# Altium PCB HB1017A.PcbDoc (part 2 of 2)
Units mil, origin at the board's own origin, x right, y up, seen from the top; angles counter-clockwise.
Board outline 2906.96 x 3469.35 mil, 2 copper layers (Top Layer, Bottom Layer); 52 components, 64 nets, 277 pads, 519 vias.
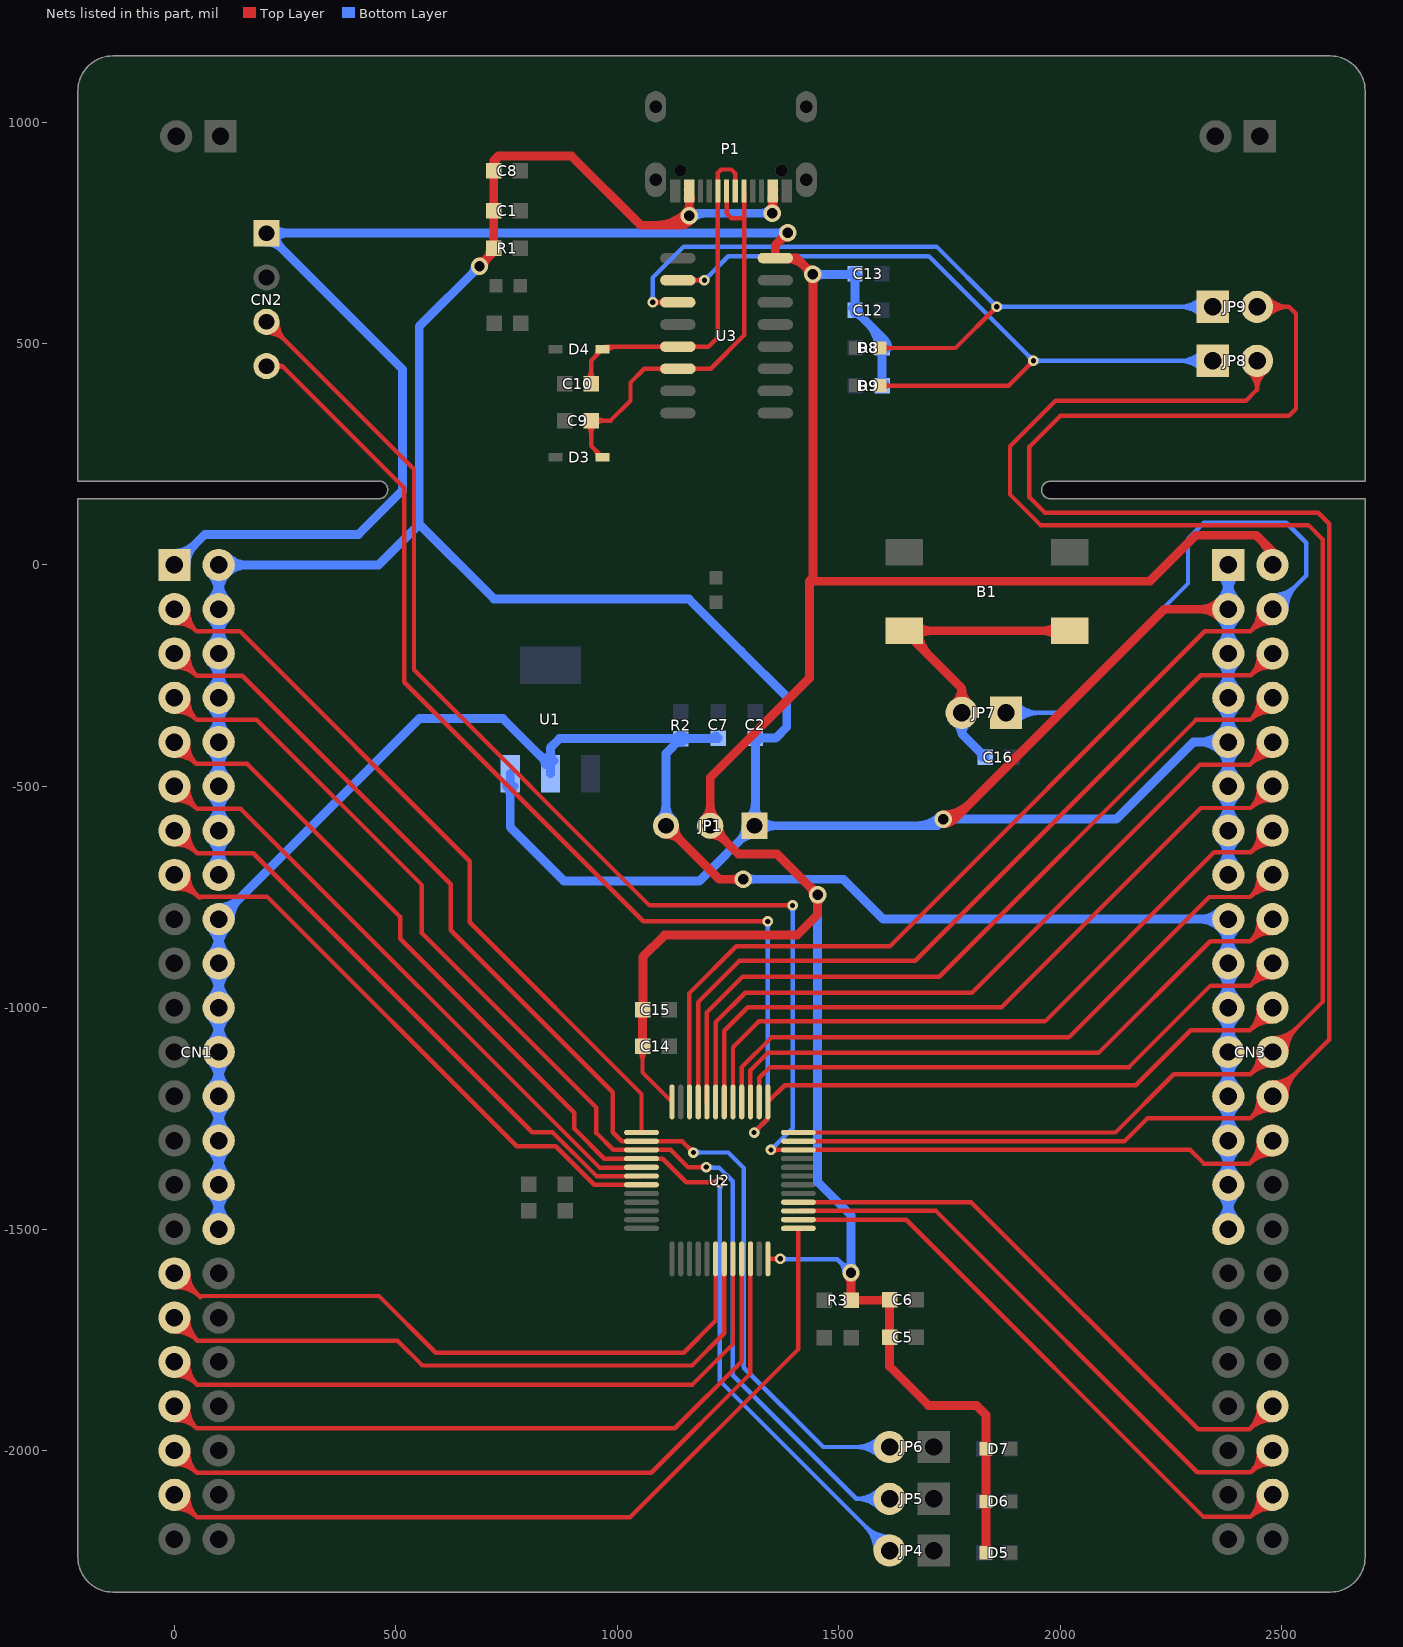
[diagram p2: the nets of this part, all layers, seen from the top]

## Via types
v1: diameter 23.62, hole 11.81, Top Layer to Bottom Layer, tented both sides, 489 vias
v2: diameter 39.37, hole 23.62, Top Layer to Bottom Layer, tented both sides, 30 vias

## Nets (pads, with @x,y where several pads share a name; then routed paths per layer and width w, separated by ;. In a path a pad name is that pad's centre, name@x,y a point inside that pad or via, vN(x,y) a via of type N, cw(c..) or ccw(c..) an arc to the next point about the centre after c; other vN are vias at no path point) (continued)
PA13: CN2.3 CN3.28 U2.34 | length 4181.5
  Top Layer w10: CN2.3@208,524.47 cw(c208,465.26) 249.87,507.13 cw(c291.74,549) CN2.3@232.53,549 ; CN2.3@208,534.47 cw(c208,499.4) 232.8,524.2 cw(c257.6,549) CN2.3@222.53,549 ; CN2.3@208,549 541,216 541,-237 1073,-769 v1(1396,-769) ; v1(1347,-1321.1) U2.34@1409.17,-1321.1 2294.14,-1321.1 2325.04,-1352 2428,-1352 ; v1@1351.82,-1325.92 cw(c1363.44,-1337.55) 1363.44,-1321.1 cw(c1363.44,-1304.66) v1@1351.82,-1316.29 ; v1@1391.18,-773.82 ccw(c1379.56,-785.44) 1379.56,-769 ccw(c1379.56,-752.56) v1@1391.18,-764.18 ; CN3.28@2448.59,-1300.7 cw(c2378.26,-1302.25) 2428,-1352 ; CN3.28@2458.59,-1300.47 cw(c2410.64,-1301.54) 2444.55,-1335.45 cw(c2478.46,-1369.36) CN3.28@2479.53,-1321.41 ; CN3.28@2479.3,-1331.41 ccw(c2477.75,-1401.74) 2428,-1352 ; CN3.28@2480,-1300 2428,-1352
  Bottom Layer w10: v1(1347,-1321.1) 1396,-1272.1 v1(1396,-769) ; v1@1347,-1314.29 ccw(c1347,-1297.85) 1358.63,-1309.47 ccw(c1370.25,-1321.1) v1@1353.81,-1321.1 ; v1@1391.18,-773.82 cw(c1379.56,-785.44) 1396,-785.44 cw(c1412.44,-785.44) v1@1400.82,-773.82
PA14: CN2.4 CN3.22 U2.37 | length 4041.1
  Top Layer w10: CN2.4@208,449 244,449 ; CN2.4@230.83,440.03 cw(c244,434.85) 244,449 ; CN2.4@230.83,457.97 ccw(c244,463.15) 244,449 ; v1(1309,-1282) 1340.27,-1250.73 U2.37@1340.27,-1212.83 1378.1,-1175 2171,-1175 2295,-1051 2429,-1051 ; v1@1309,-1275.19 ccw(c1309,-1258.75) 1320.63,-1270.37 ccw(c1332.25,-1282) v1@1315.81,-1282 ; v1@1335.18,-809.82 ccw(c1323.56,-821.44) 1323.56,-805 ccw(c1323.56,-788.56) v1@1335.18,-800.18 ; 1335.59,-1255.41 ccw(c1326.47,-1246.3) U2.37@1339.36,-1246.3 ; v1(1340,-805) 1059,-805 519,-265 519,174 244,449 ; CN3.22@2448.6,-1001.14 cw(c2381.58,-1003.57) 2429,-1051 ; CN3.22@2458.6,-1000.78 cw(c2412.9,-1002.43) 2445.24,-1034.76 cw(c2477.57,-1067.1) CN3.22@2479.22,-1021.4 ; CN3.22@2478.86,-1031.4 ccw(c2476.43,-1098.42) 2429,-1051 ; CN3.22@2480,-1000 2429,-1051
  Bottom Layer w10: v1(1309,-1282) 1340,-1251 v1(1340,-805) ; v1@1309,-1275.19 ccw(c1309,-1258.75) 1320.63,-1270.37 ccw(c1332.25,-1282) v1@1315.81,-1282 ; v1@1335.18,-809.82 cw(c1323.56,-821.44) 1340,-821.44 cw(c1356.44,-821.44) v1@1344.82,-809.82
PA15: CN3.20 U2.38 | length 1500.5
  Top Layer w10: U2.38@1320.58,-1212.83 1321,-1212.42 1321,-1158 1345,-1134 2156,-1134 2340,-950 2430,-950 ; CN3.20@2448.62,-901.6 cw(c2384.85,-904.84) 2430,-950 ; CN3.20@2458.61,-901.09 cw(c2415.13,-903.3) 2445.92,-934.08 cw(c2476.7,-964.87) CN3.20@2478.91,-921.39 ; CN3.20@2478.4,-931.38 ccw(c2475.16,-995.15) 2430,-950 ; CN3.20@2480,-900 2430,-950
PB0: CN1.33 U2.18 | length 1655.8
  Top Layer w10: CN1.33@0,-1600 5.17,-1600 56.17,-1651 462,-1651 590,-1779 1150,-1779 1222.16,-1706.84 U2.18@1222.16,-1567.17 ; CN1.33@0.99,-1621.39 cw(c3.55,-1676.75) 42.73,-1637.57 ; CN1.33@1.45,-1631.38 cw(c4.96,-1707.36) 58.75,-1653.58 ; CN1.33@21.42,-1600 ccw(c60.65,-1600) 32.91,-1627.74 ; CN1.33@31.42,-1600 ccw(c94.8,-1600) 49.98,-1644.81
PB1: CN1.35 U2.19 | length 1675.8
  Top Layer w10: CN1.35@0,-1700 52,-1752 ; CN1.35@0.47,-1721.41 cw(c1.54,-1769.36) 35.45,-1735.45 cw(c69.36,-1701.54) CN1.35@21.41,-1700.47 ; CN1.35@0.7,-1731.41 cw(c2.25,-1801.74) 52,-1752 ; CN1.35@31.41,-1700.7 ccw(c101.74,-1702.25) 52,-1752 ; U2.19@1241.84,-1567.17 1241.84,-1735.16 1169,-1808 560,-1808 504,-1752 52,-1752
PB2: CN1.37 U2.20 | length 1698.2
  Top Layer w10: CN1.37@0,-1800 51,-1851 ; CN1.37@0.78,-1821.4 cw(c2.43,-1867.1) 34.76,-1834.76 cw(c67.1,-1802.43) CN1.37@21.4,-1800.78 ; CN1.37@1.14,-1831.4 cw(c3.57,-1898.42) 51,-1851 ; CN1.37@31.4,-1801.14 ccw(c98.42,-1803.57) 51,-1851 ; U2.20@1261.53,-1567.17 1261.53,-1759.47 1170,-1851 51,-1851
PB3: CN3.18 U2.39 | length 1571.7
  Top Layer w10: U2.39@1300.9,-1212.83 1300.9,-1141.1 1340,-1102 2087,-1102 2339,-850 2430,-850 ; CN3.18@2448.62,-801.6 cw(c2384.85,-804.84) 2430,-850 ; CN3.18@2458.61,-801.09 cw(c2415.13,-803.3) 2445.92,-834.08 cw(c2476.7,-864.87) CN3.18@2478.91,-821.39 ; CN3.18@2478.4,-831.38 ccw(c2475.16,-895.15) 2430,-850 ; CN3.18@2480,-800 2430,-850
PB4: CN3.16 U2.40 | length 1637
  Top Layer w10: U2.40@1281.21,-1212.83 1281.21,-1134 1348.21,-1067 2020,-1067 2337,-750 2430,-750 ; CN3.16@2448.62,-701.6 cw(c2384.85,-704.84) 2430,-750 ; CN3.16@2458.61,-701.09 cw(c2415.13,-703.3) 2445.92,-734.08 cw(c2476.7,-764.87) CN3.16@2478.91,-721.39 ; CN3.16@2478.4,-731.38 ccw(c2475.16,-795.15) 2430,-750 ; CN3.16@2480,-700 2430,-750
PB5: CN3.14 U2.41 | length 1718.7
  Top Layer w10: U2.41@1261.53,-1212.83 1261.53,-1089 1319.53,-1031 1966,-1031 2348,-649 2431,-649 ; CN3.14@2448.65,-602.07 cw(c2388.08,-606.07) 2431,-649 ; CN3.14@2458.63,-601.41 cw(c2417.34,-604.14) 2446.6,-633.4 cw(c2475.86,-662.66) CN3.14@2478.59,-621.37 ; CN3.14@2477.93,-631.35 ccw(c2473.93,-691.92) 2431,-649 ; CN3.14@2480,-600 2431,-649
PB6: CN3.12 U2.42 | length 1801.5
  Top Layer w10: U2.42@1241.84,-1212.83 1241.84,-1052 1294.84,-999 1868,-999 2318,-549 2431,-549 ; CN3.12@2448.65,-502.07 cw(c2388.08,-506.07) 2431,-549 ; CN3.12@2458.63,-501.41 cw(c2417.34,-504.14) 2446.6,-533.4 cw(c2475.86,-562.66) CN3.12@2478.59,-521.37 ; CN3.12@2477.93,-531.35 ccw(c2473.93,-591.92) 2431,-549 ; CN3.12@2480,-500 2431,-549
PB7: CN3.10 U2.43 | length 1893.3
  Top Layer w10: U2.43@1222.16,-1212.83 1222.16,-1032.84 1289,-966 1801,-966 2316,-451 2429,-451 ; CN3.10@2448.6,-401.14 cw(c2381.58,-403.57) 2429,-451 ; CN3.10@2456,-400 CN3.10@2464,-400 ; CN3.10@2458.6,-400.78 cw(c2412.9,-402.43) 2445.24,-434.76 cw(c2477.57,-467.1) CN3.10@2479.22,-421.4 ; CN3.10@2478.86,-431.4 ccw(c2476.43,-498.42) 2429,-451 ; CN3.10@2480,-400 2429,-451
PB8: CN3.6 U2.45 | length 2022.7
  Top Layer w10: U2.45@1182.79,-1212.83 1182.79,-987.21 1276,-894 1673,-894 2318,-249 2431,-249 ; CN3.6@2448.65,-202.07 cw(c2388.08,-206.07) 2431,-249 ; CN3.6@2458.63,-201.41 cw(c2417.34,-204.14) 2446.6,-233.4 cw(c2475.86,-262.66) CN3.6@2478.59,-221.37 ; CN3.6@2477.93,-231.35 ccw(c2473.93,-291.92) 2431,-249 ; CN3.6@2480,-200 2431,-249
PB9: CN3.4 JP7.1 U2.46 | length 3617.2
  Top Layer w10: U2.46@1163.1,-1212.83 1163.1,-966.9 1269,-861 1616,-861 2327,-150 2430,-150 ; CN3.4@2448.62,-101.6 cw(c2384.85,-104.84) 2430,-150 ; CN3.4@2458.61,-101.09 cw(c2415.13,-103.3) 2445.92,-134.08 cw(c2476.7,-164.87) CN3.4@2478.91,-121.39 ; CN3.4@2478.4,-131.38 ccw(c2475.16,-195.15) 2430,-150 ; CN3.4@2480,-100 2430,-150
  Bottom Layer w10: JP7.1@1878,-334 1997,-334 2289,-42 2289,59 2325,95 2511,95 2556,50 2556,-24 CN3.4@2480,-100 ; JP7.1@1893.14,-349.14 cw(c1929.71,-385.71) 1929.71,-334 cw(c1929.71,-282.29) JP7.1@1893.14,-318.86 ; JP7.1@1900.22,-356.22 cw(c1953.85,-409.85) 1953.85,-334 cw(c1953.85,-258.15) JP7.1@1900.22,-311.78 ; CN3.4@2480,-78.58 ccw(c2480,-26.88) 2516.56,-63.44 ccw(c2553.12,-100) CN3.4@2501.42,-100 ; CN3.4@2480,-68.58 ccw(c2480,7.27) 2533.63,-46.37 ccw(c2587.27,-100) CN3.4@2511.42,-100
PB10: CN1.39 U2.21 | length 1775.8
  Top Layer w10: CN1.39@0,-1900 50,-1950 ; CN1.39@1.09,-1921.39 cw(c3.3,-1964.87) 34.08,-1934.08 cw(c64.87,-1903.3) CN1.39@21.39,-1901.09 ; CN1.39@1.6,-1931.38 cw(c4.84,-1995.15) 50,-1950 ; CN1.39@31.38,-1901.6 ccw(c95.15,-1904.84) 50,-1950 ; U2.21@1281.21,-1567.17 1281.21,-1798.79 1130,-1950 50,-1950
PB11: CN1.41 U2.22 | length 1852.9
  Top Layer w10: CN1.41@0,-2000 50,-2050 ; CN1.41@1.09,-2021.39 cw(c3.3,-2064.87) 34.08,-2034.08 cw(c64.87,-2003.3) CN1.41@21.39,-2001.09 ; CN1.41@1.6,-2031.38 cw(c4.84,-2095.15) 50,-2050 ; CN1.41@31.38,-2001.6 ccw(c95.15,-2004.84) 50,-2050 ; U2.22@1300.9,-1567.17 1300.9,-1826.1 1077,-2050 50,-2050
PB12: CN1.43 U2.25 | length 2045.7
  Top Layer w10: CN1.43@0,-2100 51,-2151 ; CN1.43@0.78,-2121.4 cw(c2.43,-2167.1) 34.76,-2134.76 cw(c67.1,-2102.43) CN1.43@21.4,-2100.78 ; CN1.43@1.14,-2131.4 cw(c3.57,-2198.42) 51,-2151 ; CN1.43@31.4,-2101.14 ccw(c98.42,-2103.57) 51,-2151 ; U2.25@1409.17,-1498.27 1409.17,-1770.83 1029,-2151 51,-2151
PB13: CN3.44 U2.26 | length 1549.3
  Top Layer w10: U2.26@1409.17,-1478.58 1409.58,-1479 1653,-1479 2324,-2150 2430,-2150 ; CN3.44@2448.62,-2101.6 cw(c2384.85,-2104.84) 2430,-2150 ; CN3.44@2458.61,-2101.09 cw(c2415.13,-2103.3) 2445.92,-2134.08 cw(c2476.7,-2164.87) CN3.44@2478.91,-2121.39 ; CN3.44@2478.4,-2131.38 ccw(c2475.16,-2195.15) 2430,-2150 ; CN3.44@2480,-2100 2430,-2150
PB14: CN3.42 U2.27 | length 1509.4
  Top Layer w10: U2.27@1409.17,-1458.9 1719.9,-1458.9 2310,-2049 2431,-2049 ; CN3.42@2448.65,-2002.07 cw(c2388.08,-2006.07) 2431,-2049 ; CN3.42@2458.63,-2001.41 cw(c2417.34,-2004.14) 2446.6,-2033.4 cw(c2475.86,-2062.66) CN3.42@2478.59,-2021.37 ; CN3.42@2477.93,-2031.35 ccw(c2473.93,-2091.92) 2431,-2049 ; CN3.42@2480,-2000 2431,-2049
PB15: CN3.40 U2.28 | length 1495.9
  Top Layer w10: U2.28@1409.17,-1439.21 1799.21,-1439.21 2312,-1952 2428,-1952 ; CN3.40@2448.59,-1900.7 cw(c2378.26,-1902.25) 2428,-1952 ; CN3.40@2458.59,-1900.47 cw(c2410.64,-1901.54) 2444.55,-1935.45 cw(c2478.46,-1969.36) CN3.40@2479.53,-1921.41 ; CN3.40@2479.3,-1931.41 ccw(c2477.75,-2001.74) 2428,-1952 ; CN3.40@2480,-1900 2428,-1952
PC0: CN1.5 JP6.2 U2.2 | length 3166.7
  Top Layer w10: CN1.5@0,-200 50,-250 ; CN1.5@1.09,-221.39 cw(c3.3,-264.87) 34.08,-234.08 cw(c64.87,-203.3) CN1.5@21.39,-201.09 ; CN1.5@1.6,-231.38 cw(c4.84,-295.15) 50,-250 ; CN1.5@31.38,-201.6 ccw(c95.15,-204.84) 50,-250 ; v1@1165.19,-1327 ccw(c1148.75,-1327) 1160.37,-1315.37 ccw(c1172,-1303.75) v1@1172,-1320.19 ; v1(1172,-1327) 1146.42,-1301.42 U2.2@1054.83,-1301.42 1010.42,-1301.42 990,-1281 990,-1191 624,-825 624,-721 153,-250 50,-250
  Bottom Layer w10: v1(1172,-1327) 1251,-1327 1286,-1362 1286,-1813 1465,-1992 JP6.2@1615,-1992 ; v1@1176.82,-1331.82 cw(c1188.44,-1343.44) 1188.44,-1327 cw(c1188.44,-1310.56) v1@1176.82,-1322.18 ; JP6.2@1592.78,-2014.22 ccw(c1539.15,-2067.85) 1539.15,-1992 ccw(c1539.15,-1916.15) JP6.2@1592.78,-1969.78 ; JP6.2@1599.86,-2007.14 ccw(c1563.29,-2043.71) 1563.29,-1992 ccw(c1563.29,-1940.29) JP6.2@1599.86,-1976.86
PC1: CN1.7 JP5.2 U2.3 | length 3146.3
  Top Layer w10: CN1.7@0,-300 50,-350 ; CN1.7@1.09,-321.39 cw(c3.3,-364.87) 34.08,-334.08 cw(c64.87,-303.3) CN1.7@21.39,-301.09 ; CN1.7@1.6,-331.38 cw(c4.84,-395.15) 50,-350 ; CN1.7@31.38,-301.6 ccw(c95.15,-304.84) 50,-350 ; v1@1196.18,-1364.82 ccw(c1184.56,-1376.44) 1184.56,-1360 ccw(c1184.56,-1343.56) v1@1196.18,-1355.18 ; v1(1201,-1360) 1160,-1360 1121.1,-1321.1 U2.3@1054.83,-1321.1 1054.73,-1321 991,-1321 953,-1283 953,-1226 559,-832 559,-723 186,-350 50,-350
  Bottom Layer w10: v1(1201,-1360) 1202,-1361 1229.85,-1361 1261,-1392.15 1261,-1830 1540,-2109 ; v1@1205.82,-1364.82 cw(c1215.03,-1374.03) 1215.03,-1361 ; v1@1205.82,-1355.18 ccw(c1219.86,-1341.14) 1219.86,-1361 ; JP5.2@1592.61,-2131.04 ccw(c1540,-2182.8) 1540,-2109 ; JP5.2@1592.61,-2086.96 cw(c1540,-2035.2) 1540,-2109 ; JP5.2@1599.73,-2124.02 ccw(c1563.88,-2159.31) 1563.88,-2109 ccw(c1563.88,-2058.69) JP5.2@1599.73,-2093.98 ; JP5.2@1615,-2109 1540,-2109
PC2: CN1.9 JP4.2 U2.4 | length 3110.2
  Top Layer w10: CN1.9@0,-400 49,-449 ; CN1.9@1.41,-421.37 cw(c4.14,-462.66) 33.4,-433.4 cw(c62.66,-404.14) CN1.9@21.37,-401.41 ; CN1.9@2.07,-431.35 cw(c6.07,-491.92) 49,-449 ; CN1.9@31.35,-402.07 ccw(c91.92,-406.07) 49,-449 ; v1@1227.18,-1398.82 ccw(c1215.56,-1410.44) 1215.56,-1394 ccw(c1215.56,-1377.56) v1@1227.18,-1389.18 ; v1(1232,-1394) 1155.76,-1394 1102.55,-1340.79 U2.4@1054.83,-1340.79 1054.62,-1341 971,-1341 903,-1273 903,-1237 510,-844 510,-795 164,-449 49,-449
  Bottom Layer w10: v1@1227.18,-1398.82 cw(c1215.56,-1410.44) 1232,-1410.44 cw(c1248.44,-1410.44) v1@1236.82,-1398.82 ; v1(1232,-1394) 1232,-1843 JP4.2@1615,-2226 ; JP4.2@1583.58,-2226 ccw(c1507.73,-2226) 1561.37,-2172.37 ccw(c1615,-2118.73) JP4.2@1615,-2194.58 ; JP4.2@1593.58,-2226 ccw(c1541.88,-2226) 1578.44,-2189.44 ccw(c1615,-2152.88) JP4.2@1615,-2204.58
PC3: CN1.11 U2.5 | length 1597
  Top Layer w10: CN1.11@0,-500 51,-551 ; CN1.11@0.78,-521.4 cw(c2.43,-567.1) 34.76,-534.76 cw(c67.1,-502.43) CN1.11@21.4,-500.78 ; CN1.11@1.14,-531.4 cw(c3.57,-598.42) 51,-551 ; CN1.11@31.4,-501.14 ccw(c98.42,-503.57) 51,-551 ; U2.5@1054.83,-1360.47 1054.31,-1361 960,-1361 150,-551 51,-551
PC4: CN1.13 U2.6 | length 1563.3
  Top Layer w10: CN1.13@0,-600 51,-651 ; CN1.13@0.78,-621.4 cw(c2.43,-667.1) 34.76,-634.76 cw(c67.1,-602.43) CN1.13@21.4,-600.78 ; CN1.13@1.14,-631.4 cw(c3.57,-698.42) 51,-651 ; CN1.13@31.4,-601.14 ccw(c98.42,-603.57) 51,-651 ; U2.6@1054.83,-1380.16 953.16,-1380.16 854,-1281 808,-1281 178,-651 51,-651
PC5: CN1.15 U2.7 | length 1528.9
  Top Layer w10: CN1.15@0,-700 5.17,-700 54.17,-749 209,-749 773,-1313 861,-1313 947.84,-1399.84 U2.7@1054.83,-1399.84 ; CN1.15@1.57,-721.36 cw(c5.3,-772.14) 41.3,-736.14 ; CN1.15@2.3,-731.33 cw(c7.41,-800.91) 56.75,-751.58 ; CN1.15@21.42,-700 ccw(c60.65,-700) 32.91,-727.74 ; CN1.15@31.42,-700 ccw(c94.8,-700) 49.98,-744.81
PC8: CN3.26 JP9.2 U2.35 | length 4785.8
  Top Layer w10: U2.35@1409.17,-1301.42 2145.58,-1301.42 2197,-1250 2430,-1250 ; JP9.2@2445,583 2517,583 ; CN3.26@2448.62,-1201.6 cw(c2384.85,-1204.84) 2430,-1250 ; CN3.26@2458.61,-1201.09 cw(c2415.13,-1203.3) 2445.92,-1234.08 cw(c2476.7,-1264.87) CN3.26@2478.91,-1221.39 ; JP9.2@2460.7,568.43 cw(c2494.08,537.47) 2494.08,583 cw(c2494.08,628.53) JP9.2@2460.7,597.57 ; JP9.2@2468.03,561.63 cw(c2517,516.21) 2517,583 ; JP9.2@2468.03,604.37 ccw(c2517,649.79) 2517,583 ; CN3.26@2478.4,-1231.38 ccw(c2475.16,-1295.15) 2430,-1250 ; CN3.26@2480,-1178.58 ccw(c2480,-1126.88) 2516.56,-1163.44 ccw(c2553.12,-1200) CN3.26@2501.42,-1200 ; CN3.26@2480,-1168.58 ccw(c2480,-1092.73) 2533.63,-1146.37 ccw(c2587.27,-1200) CN3.26@2511.42,-1200 ; 2430,-1250 CN3.26@2480,-1200 2608,-1072 2608,93 2583,118 1966,118 1931,153 1931,267 2001,337 2517,337 2533,353 2533,567 2517,583
PC9: CN3.24 JP8.2 U2.36 | length 4419.8
  Top Layer w10: U2.36@1409.17,-1281.73 2125.27,-1281.73 2257,-1150 2430,-1150 ; JP8.2@2425.48,436.38 cw(c2393.47,396) 2445,396 ; JP8.2@2431.7,444.22 cw(c2409.88,416.69) 2445,416.69 cw(c2480.12,416.69) JP8.2@2458.3,444.22 ; JP8.2@2445,461 2445,396 ; CN3.24@2448.62,-1101.6 cw(c2384.85,-1104.84) 2430,-1150 ; CN3.24@2458.61,-1101.09 cw(c2415.13,-1103.3) 2445.92,-1134.08 cw(c2476.7,-1164.87) CN3.24@2478.91,-1121.39 ; JP8.2@2464.52,436.38 ccw(c2496.53,396) 2445,396 ; CN3.24@2478.4,-1131.38 ccw(c2475.16,-1195.15) 2430,-1150 ; CN3.24@2480,-1078.58 ccw(c2480,-1026.88) 2516.56,-1063.44 ccw(c2553.12,-1100) CN3.24@2501.42,-1100 ; CN3.24@2480,-1068.58 ccw(c2480,-992.73) 2533.63,-1046.37 ccw(c2587.27,-1100) CN3.24@2511.42,-1100 ; 2430,-1150 CN3.24@2480,-1100 2593,-987 2593,58 2561,90 1956,90 1887,159 1887,268 1990,371 2420,371 2445,396
PC10: CN3.8 U2.44 | length 1953.8
  Top Layer w10: U2.44@1202.47,-1212.83 1202.47,-1010.53 1283,-930 1727,-930 2307,-350 2430,-350 ; CN3.8@2448.62,-301.6 cw(c2384.85,-304.84) 2430,-350 ; CN3.8@2458.61,-301.09 cw(c2415.13,-303.3) 2445.92,-334.08 cw(c2476.7,-364.87) CN3.8@2478.91,-321.39 ; CN3.8@2478.4,-331.38 ccw(c2475.16,-395.15) 2430,-350 ; CN3.8@2480,-300 2430,-350
PC11: CN1.3 U2.1 | length 1855.7
  Top Layer w10: CN1.3@0,-100 50,-150 ; CN1.3@1.09,-121.39 cw(c3.3,-164.87) 34.08,-134.08 cw(c64.87,-103.3) CN1.3@21.39,-101.09 ; CN1.3@1.6,-131.38 cw(c4.84,-195.15) 50,-150 ; CN1.3@31.38,-101.6 ccw(c95.15,-104.84) 50,-150 ; U2.1@1054.83,-1281.73 1054.83,-1194.83 667,-807 667,-669 148,-150 50,-150
UART_RX: D9.2 JP8.1 U3.2 | length 2092.3
  Top Layer w10: U3.2@1137,643 v1(1197,643) ; U3.2@1169.95,638.05 cw(c1181.9,626.1) 1181.9,643 cw(c1181.9,659.9) U3.2@1169.95,647.95 ; v1@1192.18,638.18 ccw(c1180.56,626.56) 1180.56,643 ccw(c1180.56,659.44) v1@1192.18,647.82 ; D9.2@1593,405 1884,405 v1(1940,461) ; D9.2@1600.07,397.93 cw(c1617.14,380.86) 1617.14,405 cw(c1617.14,429.14) D9.2@1600.07,412.07 ; v1@1933.19,461 cw(c1916.75,461) 1928.37,449.37 cw(c1940,437.75) v1@1940,454.19
  Bottom Layer w10: v1(1197,643) 1251,697 1704,697 v1(1940,461) JP8.1@2345,461 ; v1@1197,649.81 ccw(c1197,666.25) 1208.63,654.63 ccw(c1220.25,643) v1@1203.81,643 ; v1@1933.19,461 ccw(c1916.75,461) 1928.37,472.63 ccw(c1940,484.25) v1@1940,467.81 ; v1@1944.82,456.18 cw(c1956.44,444.56) 1956.44,461 cw(c1956.44,477.44) v1@1944.82,465.82 ; JP8.1@2322.78,438.78 ccw(c2269.15,385.15) 2269.15,461 ccw(c2269.15,536.85) JP8.1@2322.78,483.22 ; JP8.1@2329.86,445.86 ccw(c2293.29,409.29) 2293.29,461 ccw(c2293.29,512.71) JP8.1@2329.86,476.14
UART_TX: D8.2 JP9.1 U3.3 | length 2159.8
  Top Layer w10: v1(1080,593) U3.3@1137,593 ; v1@1084.82,588.18 cw(c1096.44,576.56) 1096.44,593 cw(c1096.44,609.44) v1@1084.82,597.82 ; U3.3@1104.05,588.05 ccw(c1092.1,576.1) 1092.1,593 ccw(c1092.1,609.9) U3.3@1104.05,597.95 ; D8.2@1593,490 1744,490 1764,490 v1(1857,583) ; D8.2@1600.07,482.93 cw(c1617.14,465.86) 1617.14,490 cw(c1617.14,514.14) D8.2@1600.07,497.07 ; v1@1850.19,583 cw(c1833.75,583) 1845.37,571.37 cw(c1857,559.75) v1@1857,576.19
  Bottom Layer w10: v1@1075.18,597.82 ccw(c1063.56,609.44) 1080,609.44 ccw(c1096.44,609.44) v1@1084.82,597.82 ; v1(1080,593) 1080,649 1150,719 1721,719 v1(1857,583) JP9.1@2345,583 ; v1@1850.19,583 ccw(c1833.75,583) 1845.37,594.63 ccw(c1857,606.25) v1@1857,589.81 ; v1@1861.82,578.18 cw(c1873.44,566.56) 1873.44,583 cw(c1873.44,599.44) v1@1861.82,587.82 ; JP9.1@2322.78,560.78 ccw(c2269.15,507.15) 2269.15,583 ccw(c2269.15,658.85) JP9.1@2322.78,605.22 ; JP9.1@2329.86,567.86 ccw(c2293.29,531.29) 2293.29,583 ccw(c2293.29,634.71) JP9.1@2329.86,598.14
USB_N: C9.2 D3.2 P1.A7 P1.B7 U3.6 | length 1132.9
  Top Layer w10: C9.2@932.11,317.16 cw(c910.78,295.82) 940.95,295.82 cw(c971.13,295.82) 949.79,317.16 cw(c971.13,295.82) 971.13,326 cw(c971.13,356.18) C9.2@949.79,334.84 ; 948.65,261.35 cw(c930.3,243) D3.2@956.25,243 ; D3.2@967,243 940.95,269.05 C9.2@940.95,326 985,326 1030,371 1030,412 1061,443 U3.6@1137,443 1211,443 1286.45,518.45 1286.45,786 ; U3.6@1104.05,438.05 ccw(c1092.1,426.1) 1092.1,443 ccw(c1092.1,459.9) U3.6@1104.05,447.95 ; U3.6@1169.95,438.05 cw(c1181.9,426.1) 1181.9,443 cw(c1181.9,459.9) U3.6@1169.95,447.95 ; P1.A7@1247.08,844.4 1247.08,793.92 1258,783 1283.45,783 1286.45,786 ; P1.B7@1286.45,844.4 1286.45,786
USB_P: C10.1 D4.1 P1.A6 P1.B6 U3.5 | length 960.5
  Top Layer w10: C10.1@932.11,418.16 ccw(c910.78,439.5) 940.95,439.5 ccw(c971.13,439.5) C10.1@949.79,418.16 ; C10.1@940.95,409.32 940.95,460.95 D4.1@967,487 973,493 U3.5@1137,493 1206,493 1227.39,514.39 P1.B6@1227.39,844.4 1227.39,885.39 1233,891 ; 948.65,468.65 ccw(c930.3,487) D4.1@956.25,487 ; D4.1@976.33,483.58 cw(c999.08,460.82) 999.08,493 ; U3.5@1104.05,488.05 ccw(c1092.1,476.1) 1092.1,493 ccw(c1092.1,509.9) U3.5@1104.05,497.95 ; U3.5@1169.95,488.05 cw(c1181.9,476.1) 1181.9,493 cw(c1181.9,509.9) U3.5@1169.95,497.95 ; 1235,893 1258,893 1266.76,884.24 P1.A6@1266.76,844.4
USER_KEY: B1.3 B1.4 C16.1 JP7.2 | length 1114.9
  Top Layer w20: B1.3@1674.68,-162.67 cw(c1708.68,-196.68) 1708.68,-148.58 cw(c1708.68,-100.49) B1.3@1674.68,-134.5 ; B1.3@1680.51,-148.58 ccw(c1759.02,-148.58) 1703.51,-204.1 ; JP7.2@1761.37,-313.47 ccw(c1733.11,-278.59) 1778,-278.59 ; JP7.2@1778,-334 1778,-278.59 ; JP7.2@1794.63,-313.47 cw(c1822.89,-278.59) 1778,-278.59 ; B1.4@1995.32,-162.67 ccw(c1961.32,-196.68) 1961.32,-148.58 ccw(c1961.32,-100.49) B1.4@1995.32,-134.5 ; B1.4@2022.01,-148.58 B1.3@1647.99,-148.58 1778,-278.59
  Bottom Layer w20: JP7.2@1764.27,-356.57 cw(c1749.4,-381) 1778,-381 ; JP7.2@1778,-334 1778,-381 ; JP7.2@1791.73,-356.57 ccw(c1806.6,-381) 1778,-381 ; C16.1@1823.5,-434 ccw(c1805.39,-434) 1818.2,-421.2 ccw(c1831,-408.39) C16.1@1831,-426.5 ; C16.1@1831,-434 1778,-381
VBUS_5V: C1.2 C2.2 C8.2 CN1.2 CN1.4 CN1.6 CN1.8 CN1.10 CN1.12 CN1.14 CN1.16 CN3.1 CN3.3 CN3.5 CN3.7 CN3.9 CN3.11 CN3.13 CN3.15 JP1.1 P1.A4 P1.A9 P1.B4 P1.B9 R1.1 U1.3 | length 11961.1
  Top Layer w20: v2(689,675) 721.1,707.1 R1.1@721.1,715.66 C1.2@721.1,799.66 C8.2@721.1,890.66 721.1,913.1 731.16,923.16 ; v2@689,684.69 ccw(c689,708.07) 705.53,691.53 ccw(c722.07,675) v2@698.69,675 ; v2@702.23,688.23 ccw(c674.8,715.66) R1.1@713.6,715.66 ; R1.1@715.79,720.97 ccw(c702.99,733.77) 721.1,733.77 ccw(c739.2,733.77) R1.1@726.4,720.97 ; C1.2@715.79,794.36 cw(c702.99,781.56) 721.1,781.56 cw(c739.2,781.56) C1.2@726.4,794.36 ; C1.2@715.79,804.97 ccw(c702.99,817.77) 721.1,817.77 ccw(c739.2,817.77) C1.2@726.4,804.97 ; C8.2@715.79,885.36 cw(c702.99,872.56) 721.1,872.56 cw(c739.2,872.56) C8.2@726.4,885.36 ; C8.2@715.79,895.97 ccw(c702.99,908.77) 721.1,908.77 ccw(c739.2,908.77) C8.2@726.4,895.97 ; C8.2@727.55,894.48 cw(c747.83,906.5) 731.16,923.16 ; 1086.51,767 ccw(c1086.51,865.49) 1156.15,795.85 ccw(c1140.77,811.23) 1162.52,811.23 ; 1134.79,767 ccw(c1134.79,817.21) v2@1170.29,781.71 ; 1153,771 ccw(c1145.39,778.61) v2@1154.66,784.08 ; P1.A9@1159.42,827.62 cw(c1151.92,820.12) P1.B4@1162.52,820.12 ; P1.A9@1159.42,847.3 cw(c1151.92,839.81) P1.B4@1162.52,839.81 ; v2@1162.52,780.52 1149,767 1053,767 896.84,923.16 731.16,923.16 ; v2@1162.52,789 P1.B4@1162.52,844.41 ; 1162.52,813.54 ccw(c1187.54,813.54) v2@1169.85,795.85 ; P1.B4@1162.52,820.56 cw(c1172.51,820.56) P1.B4@1165.45,827.62 ; v2@1343.63,801.25 ccw(c1325.08,819.8) P1.B9@1351.31,819.8 ; P1.B9@1348.4,827.61 cw(c1341.36,820.57) P1.B9@1351.31,820.57 ; v2@1351.31,786.31 P1.B9@1351.31,844.4 ; 1351.31,815.77 ccw(c1371.85,815.77) v2@1357.33,801.25 ; P1.B9@1351.31,820.12 cw(c1361.91,820.12) P1.A4@1354.42,827.61 ; P1.B9@1351.31,839.8 cw(c1361.91,839.8) P1.A4@1354.42,847.3 ; v2@1736,-584.31 ccw(c1736,-548.86) 1761.07,-573.93 ; v2(1736,-574) 1761,-574 2235,-100 CN3.3@2380,-100 ; v2@1736,-564.32 ccw(c1736,-480.58) 1795.21,-539.79 ; v2@1742.85,-580.85 cw(c1759.38,-597.38) 1759.38,-574 cw(c1759.38,-550.62) v2@1742.85,-567.15 ; CN3.3@2361.32,-118.68 ccw(c2316.22,-163.78) 2316.22,-100 ccw(c2316.22,-36.22) CN3.3@2361.32,-81.32
  Bottom Layer w20: CN1.16@81.32,-681.32 ccw(c36.22,-636.22) 100,-636.22 ccw(c163.78,-636.22) CN1.16@118.68,-681.32 ; CN1.14@81.32,-618.68 cw(c36.22,-663.78) 100,-663.78 cw(c163.78,-663.78) CN1.14@118.68,-618.68 ; CN1.14@81.32,-581.32 ccw(c36.22,-536.22) 100,-536.22 ccw(c163.78,-536.22) CN1.14@118.68,-581.32 ; CN1.12@81.32,-518.68 cw(c36.22,-563.78) 100,-563.78 cw(c163.78,-563.78) CN1.12@118.68,-518.68 ; CN1.12@81.32,-481.32 ccw(c36.22,-436.22) 100,-436.22 ccw(c163.78,-436.22) CN1.12@118.68,-481.32 ; CN1.10@81.32,-418.68 cw(c36.22,-463.78) 100,-463.78 cw(c163.78,-463.78) CN1.10@118.68,-418.68 ; CN1.10@81.32,-381.32 ccw(c36.22,-336.22) 100,-336.22 ccw(c163.78,-336.22) CN1.10@118.68,-381.32 ; CN1.8@81.32,-318.68 cw(c36.22,-363.78) 100,-363.78 cw(c163.78,-363.78) CN1.8@118.68,-318.68 ; CN1.8@81.32,-281.32 ccw(c36.22,-236.22) 100,-236.22 ccw(c163.78,-236.22) CN1.8@118.68,-281.32 ; CN1.6@81.32,-218.68 cw(c36.22,-263.78) 100,-263.78 cw(c163.78,-263.78) CN1.6@118.68,-218.68 ; CN1.6@81.32,-181.32 ccw(c36.22,-136.22) 100,-136.22 ccw(c163.78,-136.22) CN1.6@118.68,-181.32 ; CN1.4@81.32,-118.68 cw(c36.22,-163.78) 100,-163.78 cw(c163.78,-163.78) CN1.4@118.68,-118.68 ; CN1.4@81.32,-81.32 ccw(c36.22,-36.22) 100,-36.22 ccw(c163.78,-36.22) CN1.4@118.68,-81.32 ; CN1.2@81.32,-18.68 cw(c36.22,-63.78) 100,-63.78 cw(c163.78,-63.78) 118.68,-18.68 cw(c163.78,-63.78) 163.78,0 cw(c163.78,63.78) CN1.2@118.68,18.68 ; CN1.16@100,-700 CN1.14@100,-600 CN1.12@100,-500 CN1.10@100,-400 CN1.8@100,-300 CN1.6@100,-200 CN1.4@100,-100 CN1.2@100,0 461,0 553,92 ; v2@679.31,675 cw(c655.93,675) 672.47,658.47 cw(c689,641.93) v2@689,665.31 ; v2(689,675) 553,539 553,92 ; U1.3@750.21,-499.96 cw(c730.31,-519.85) 758.45,-519.85 cw(c786.58,-519.85) U1.3@766.69,-499.96 ; U1.3@758.45,-471.05 758.45,-592.45 880,-714 1185,-714 JP1.1@1310,-589 ; v2(1163,789) 1168.4,794.4 v2(1350.48,794.4) ; v2@1169.85,782.15 cw(c1199.42,752.58) 1199.42,794.4 ; JP1.1@1290.47,-589 cw(c1243.33,-589) 1276.66,-622.34 cw(c1310,-655.67) JP1.1@1310,-608.53 ; JP1.1@1296.19,-575.19 ccw(c1258.03,-537.03) 1312,-537.03 ; C2.2@1306.7,-396.3 cw(c1293.89,-409.11) 1312,-409.11 cw(c1330.11,-409.11) 1317.3,-396.3 cw(c1330.11,-409.11) 1330.11,-391 cw(c1330.11,-372.89) C2.2@1317.3,-385.7 ; 1312,-546.68 ccw(c1352.32,-546.68) 1323.81,-575.19 ccw(c1357.14,-541.86) 1357.14,-589 ccw(c1357.14,-636.14) JP1.1@1323.81,-602.81 ; v2@1343.63,787.55 ccw(c1327.1,771.02) 1327.1,794.4 ccw(c1327.1,817.78) v2@1343.63,801.25 ; 1676.41,-589 ccw(c1676.41,-514.41) v2@1729.15,-567.15 ; v2(1736,-574) v2@1738,-574 ; v2@1742.85,-580.85 cw(c1759.38,-597.38) 1759.38,-574 cw(c1759.38,-550.62) v2@1742.85,-567.15 ; CN3.15@2361.32,-681.32 ccw(c2316.22,-636.22) 2380,-636.22 ccw(c2443.78,-636.22) CN3.15@2398.68,-681.32 ; CN3.13@2361.32,-618.68 cw(c2316.22,-663.78) 2380,-663.78 cw(c2443.78,-663.78) CN3.13@2398.68,-618.68 ; CN3.13@2361.32,-581.32 ccw(c2316.22,-536.22) 2380,-536.22 ccw(c2443.78,-536.22) CN3.13@2398.68,-581.32 ; CN3.11@2361.32,-518.68 cw(c2316.22,-563.78) 2380,-563.78 cw(c2443.78,-563.78) CN3.11@2398.68,-518.68 ; CN3.11@2361.32,-481.32 ccw(c2316.22,-436.22) 2380,-436.22 ccw(c2443.78,-436.22) CN3.11@2398.68,-481.32 ; CN3.7@2361.32,-318.68 cw(c2316.22,-363.78) 2380,-363.78 cw(c2443.78,-363.78) CN3.7@2398.68,-318.68 ; CN3.7@2361.32,-281.32 ccw(c2316.22,-236.22) 2380,-236.22 ccw(c2443.78,-236.22) CN3.7@2398.68,-281.32 ; CN3.5@2361.32,-218.68 cw(c2316.22,-263.78) 2380,-263.78 cw(c2443.78,-263.78) CN3.5@2398.68,-218.68 ; CN3.5@2361.32,-181.32 ccw(c2316.22,-136.22) 2380,-136.22 ccw(c2443.78,-136.22) CN3.5@2398.68,-181.32 ; CN3.3@2361.32,-118.68 cw(c2316.22,-163.78) 2380,-163.78 cw(c2443.78,-163.78) CN3.3@2398.68,-118.68 ; CN3.3@2361.32,-81.32 ccw(c2316.22,-36.22) 2380,-36.22 ccw(c2443.78,-36.22) CN3.3@2398.68,-81.32 ; CN3.1@2361.32,-18.68 cw(c2316.22,-63.78) 2380,-63.78 cw(c2443.78,-63.78) CN3.1@2398.68,-18.68 ; CN3.15@2380,-700 CN3.13@2380,-600 CN3.11@2380,-500 CN3.9@2380,-400 ; CN3.1@2380,0 CN3.3@2380,-100 CN3.5@2380,-200 CN3.7@2380,-300 CN3.9@2380,-400 ; CN3.9@2398.68,-418.68 ccw(c2443.78,-463.78) 2380,-463.78 ccw(c2316.22,-463.78) 2361.32,-418.68 ccw(c2316.22,-463.78) 2316.22,-400 ccw(c2316.22,-336.22) 2361.32,-381.32 ccw(c2316.22,-336.22) 2380,-336.22 ccw(c2443.78,-336.22) CN3.9@2398.68,-381.32 ; 553,92 722,-77 1162,-77 1279.5,-194.5 1383,-298 1383,-366 1358,-391 C2.2@1312,-391 1312,-587 JP1.1@1310,-589 ; JP1.1@1310,-589 1723,-589 v2@1738,-574 ; v2@1738,-574 2127,-574 2301,-400 CN3.9@2380,-400
VCC_3V3: C7.2 CN1.18 CN1.20 CN1.22 CN1.24 CN1.26 CN1.28 CN1.30 CN1.32 CN3.17 CN3.19 CN3.21 CN3.23 CN3.25 CN3.27 CN3.29 CN3.31 JP1.3 R2.2 U1.2 | length 7815.7
  Top Layer w20: JP1.3@1110,-608.53 cw(c1110,-655.67) 1143.34,-622.34 cw(c1176.67,-589) JP1.3@1129.53,-589 ; JP1.3@1110,-589 1230.81,-709.81 v2(1284.19,-709.81) ; v2@1277.34,-716.66 ccw(c1260.8,-733.2) 1260.8,-709.81 ccw(c1260.8,-686.43) v2@1277.34,-702.97
  Bottom Layer w10: 1079,-392 1080,-391
  Bottom Layer w20: CN1.32@81.32,-1481.32 ccw(c36.22,-1436.22) 100,-1436.22 ccw(c163.78,-1436.22) CN1.32@118.68,-1481.32 ; CN1.30@81.32,-1418.68 cw(c36.22,-1463.78) 100,-1463.78 cw(c163.78,-1463.78) CN1.30@118.68,-1418.68 ; CN1.30@81.32,-1381.32 ccw(c36.22,-1336.22) 100,-1336.22 ccw(c163.78,-1336.22) CN1.30@118.68,-1381.32 ; CN1.28@81.32,-1318.68 cw(c36.22,-1363.78) 100,-1363.78 cw(c163.78,-1363.78) CN1.28@118.68,-1318.68 ; CN1.28@81.32,-1281.32 ccw(c36.22,-1236.22) 100,-1236.22 ccw(c163.78,-1236.22) CN1.28@118.68,-1281.32 ; CN1.26@81.32,-1218.68 cw(c36.22,-1263.78) 100,-1263.78 cw(c163.78,-1263.78) CN1.26@118.68,-1218.68 ; CN1.26@81.32,-1181.32 ccw(c36.22,-1136.22) 100,-1136.22 ccw(c163.78,-1136.22) CN1.26@118.68,-1181.32 ; CN1.24@81.32,-1118.68 cw(c36.22,-1163.78) 100,-1163.78 cw(c163.78,-1163.78) CN1.24@118.68,-1118.68 ; CN1.24@81.32,-1081.32 ccw(c36.22,-1036.22) 100,-1036.22 ccw(c163.78,-1036.22) CN1.24@118.68,-1081.32 ; CN1.22@81.32,-1018.68 cw(c36.22,-1063.78) 100,-1063.78 cw(c163.78,-1063.78) CN1.22@118.68,-1018.68 ; CN1.22@81.32,-981.32 ccw(c36.22,-936.22) 100,-936.22 ccw(c163.78,-936.22) CN1.22@118.68,-981.32 ; CN1.20@81.32,-918.68 cw(c36.22,-963.78) 100,-963.78 cw(c163.78,-963.78) CN1.20@118.68,-918.68 ; CN1.20@81.32,-881.32 ccw(c36.22,-836.22) 100,-836.22 ccw(c163.78,-836.22) CN1.20@118.68,-881.32 ; CN1.18@81.32,-818.68 cw(c36.22,-863.78) 100,-863.78 cw(c163.78,-863.78) CN1.18@118.68,-818.68 ; CN1.32@100,-1500 CN1.30@100,-1400 CN1.28@100,-1300 CN1.26@100,-1200 CN1.24@100,-1100 CN1.22@100,-1000 CN1.20@100,-900 CN1.18@100,-800 553,-347 742,-347 849,-454 U1.2@849,-471.05 849,-412.98 869.98,-392 1079,-392 R2.2@1144,-392 ; CN1.18@100,-773.58 ccw(c100,-709.81) 145.1,-754.9 ccw(c190.19,-800) CN1.18@126.42,-800 ; 822.92,-427.92 ccw(c849,-401.84) U1.2@849,-438.72 ; U1.2@831.67,-436.67 cw(c817.96,-450.38) U1.2@837.35,-450.38 ; U1.2@840.76,-442.14 ccw(c820.87,-422.24) 849,-422.24 ccw(c877.13,-422.24) U1.2@857.24,-442.14 ; JP1.3@1096.19,-575.19 ccw(c1062.86,-541.86) 1110,-541.86 ccw(c1157.14,-541.86) JP1.3@1123.81,-575.19 ; JP1.3@1110,-589 1110,-426 R2.2@1144,-392 ; R2.2@1136.5,-392 cw(c1118.39,-392) 1131.2,-404.8 cw(c1144,-417.61) R2.2@1144,-399.5 ; R2.2@1138.7,-397.3 ccw(c1125.89,-410.11) 1125.89,-392 ccw(c1125.89,-373.89) R2.2@1138.7,-386.7 ; R2.2@1149.3,-397.3 cw(c1162.11,-410.11) 1162.11,-392 cw(c1162.11,-373.89) R2.2@1149.3,-386.7 ; 1207.48,-392 ccw(c1207.48,-370.48) C7.2@1222.7,-385.7 ; C7.2@1228,-391 1227,-392 R2.2@1144,-392 ; v2(1284.19,-709.81) 1510.81,-709.81 1601,-800 CN3.17@2364,-800 ; v2@1291.03,-716.66 cw(c1307.57,-733.2) 1307.57,-709.81 cw(c1307.57,-686.43) v2@1291.03,-702.97 ; CN3.31@2361.32,-1481.32 ccw(c2316.22,-1436.22) 2380,-1436.22 ccw(c2443.78,-1436.22) CN3.31@2398.68,-1481.32 ; CN3.29@2361.32,-1418.68 cw(c2316.22,-1463.78) 2380,-1463.78 cw(c2443.78,-1463.78) CN3.29@2398.68,-1418.68 ; CN3.29@2361.32,-1381.32 ccw(c2316.22,-1336.22) 2380,-1336.22 ccw(c2443.78,-1336.22) CN3.29@2398.68,-1381.32 ; CN3.27@2361.32,-1318.68 cw(c2316.22,-1363.78) 2380,-1363.78 cw(c2443.78,-1363.78) CN3.27@2398.68,-1318.68 ; CN3.27@2361.32,-1281.32 ccw(c2316.22,-1236.22) 2380,-1236.22 ccw(c2443.78,-1236.22) CN3.27@2398.68,-1281.32 ; CN3.25@2361.32,-1218.68 cw(c2316.22,-1263.78) 2380,-1263.78 cw(c2443.78,-1263.78) CN3.25@2398.68,-1218.68 ; CN3.25@2361.32,-1181.32 ccw(c2316.22,-1136.22) 2380,-1136.22 ccw(c2443.78,-1136.22) CN3.25@2398.68,-1181.32 ; CN3.23@2361.32,-1118.68 cw(c2316.22,-1163.78) 2380,-1163.78 cw(c2443.78,-1163.78) CN3.23@2398.68,-1118.68 ; CN3.23@2361.32,-1081.32 ccw(c2316.22,-1036.22) 2380,-1036.22 ccw(c2443.78,-1036.22) CN3.23@2398.68,-1081.32 ; CN3.21@2361.32,-1018.68 cw(c2316.22,-1063.78) 2380,-1063.78 cw(c2443.78,-1063.78) CN3.21@2398.68,-1018.68 ; CN3.21@2361.32,-981.32 ccw(c2316.22,-936.22) 2380,-936.22 ccw(c2443.78,-936.22) CN3.21@2398.68,-981.32 ; CN3.19@2361.32,-918.68 cw(c2316.22,-963.78) 2380,-963.78 cw(c2443.78,-963.78) CN3.19@2398.68,-918.68 ; CN3.19@2361.32,-881.32 ccw(c2316.22,-836.22) 2380,-836.22 ccw(c2443.78,-836.22) CN3.19@2398.68,-881.32 ; CN3.17@2361.32,-781.32 cw(c2316.22,-736.22) 2316.22,-800 cw(c2316.22,-863.78) 2361.32,-818.68 cw(c2316.22,-863.78) 2380,-863.78 cw(c2443.78,-863.78) CN3.17@2398.68,-818.68 ; CN3.31@2380,-1500 CN3.29@2380,-1400 CN3.27@2380,-1300 CN3.25@2380,-1200 CN3.23@2380,-1100 CN3.21@2380,-1000 CN3.19@2380,-900 CN3.17@2380,-800
VCC_MCU: C5.1 C6.1 C12.2 C13.2 C14.2 C15.2 CN1.1 CN2.1 CN3.2 D5.1 D6.1 D7.1 JP1.2 R3.2 R8.1 R9.1 U2.24 U2.48 U3.16 | length 10143.3
  Top Layer w10: C14.2@1048.26,-1096.18 cw(c1026.92,-1117.52) 1057.1,-1117.52 cw(c1087.27,-1117.52) C14.2@1065.93,-1096.18 ; C14.2@1057.1,-1087.34 1057.1,-1146.2 U2.48@1123.73,-1212.83 ; U2.24@1340.27,-1567.17 v1(1368,-1567.16) ; v1@1363.18,-1571.98 ccw(c1351.56,-1583.61) 1351.56,-1567.17 ccw(c1351.56,-1550.72) v1@1363.18,-1562.35 ; R3.2@1528,-1660.57 R3.2@1529,-1659.57 ; C6.1@1614,-1660.57 C6.1@1615,-1659.57
  Top Layer w20: C14.2@1051.79,-1082.03 ccw(c1038.99,-1069.23) 1057.1,-1069.23 ccw(c1075.2,-1069.23) C14.2@1062.4,-1082.03 ; C15.2@1051.79,-1009.64 cw(c1038.99,-1022.44) 1057.1,-1022.44 cw(c1075.2,-1022.44) C15.2@1062.4,-1009.64 ; C15.2@1051.79,-999.03 ccw(c1036.8,-984.05) 1058,-984.05 ; C14.2@1057.1,-1087.34 C15.2@1057.1,-1004.34 1058,-1003.43 1058,-885 1107,-836 1406,-836 1452.5,-789.5 v2(1452.5,-744.5) 1361,-653 1321,-653 1274,-653 JP1.2@1210,-589 1210,-480 1434,-256 1434,-37 ; JP1.2@1196.19,-575.19 ccw(c1162.86,-541.86) 1210,-541.86 ccw(c1257.14,-541.86) JP1.2@1223.81,-575.19 ; JP1.2@1210,-608.53 cw(c1210,-655.67) 1243.34,-622.34 cw(c1276.67,-589) JP1.2@1229.53,-589 ; v2@1375.31,750 cw(c1351.93,750) 1368.47,733.47 cw(c1385,716.93) v2@1385,740.31 ; U3.16@1385,691 cw(c1385,637.89) 1422.56,675.44 ; v2(1385,750) 1357,722 U3.16@1357,693 1405,693 v2(1442,656) 1442,-29 1434,-37 ; U3.16@1385.5,691.06 cw(c1393.19,661.19) 1415,683 ; v2@1432.31,656 ccw(c1408.93,656) 1425.47,672.53 ccw(c1442,689.07) v2@1442,665.69 ; v2@1435.15,649.15 cw(c1418.62,632.62) 1442,632.62 cw(c1465.38,632.62) v2@1448.85,649.15 ; v2@1442.81,-744.5 ccw(c1419.43,-744.5) 1435.97,-727.97 ccw(c1452.5,-711.43) v2@1452.5,-734.82 ; v2@1445.65,-751.35 cw(c1429.12,-767.88) 1452.5,-767.88 cw(c1475.88,-767.88) v2@1459.35,-751.35 ; v2@1521.15,-1605.85 cw(c1504.62,-1622.38) 1528,-1622.38 cw(c1551.38,-1622.38) v2@1534.85,-1605.85 ; R3.2@1522.7,-1655.26 ccw(c1509.89,-1642.46) 1528,-1642.46 ccw(c1546.11,-1642.46) 1533.3,-1655.26 ccw(c1546.11,-1642.46) 1546.11,-1660.57 ccw(c1546.11,-1678.67) R3.2@1533.3,-1665.87 ; v2(1528,-1599) R3.2@1528,-1660.57 C6.1@1614,-1660.57 ; 1594.48,-1660.57 ccw(c1594.48,-1639.05) C6.1@1609.7,-1654.26 ; C5.1@1609.7,-1749.3 cw(c1596.89,-1762.11) 1615,-1762.11 cw(c1633.11,-1762.11) C5.1@1620.3,-1749.3 ; C5.1@1609.7,-1738.7 ccw(c1596.89,-1725.89) 1615,-1725.89 ccw(c1633.11,-1725.89) C5.1@1620.3,-1738.7 ; C6.1@1609.7,-1664.87 cw(c1596.89,-1677.67) 1615,-1677.67 cw(c1633.11,-1677.67) C6.1@1620.3,-1664.87 ; C5.1@1615,-1747.43 C5.1@1615,-1744 ; C6.1@1615,-1663 C5.1@1615,-1744 ; D5.1@1832.98,-2231.04 D6.1@1832.98,-2115 D7.1@1832.98,-1995.99 1832.98,-1919.98 1811,-1898 1703,-1898 1615,-1810 C5.1@1615,-1744 ; 2456.13,53.86 cw(c2412.25,9.98) CN3.2@2473.65,0.93 ; CN3.2@2480,0 2480,30 2443,67 2307,67 2203,-37 1434,-37
  Bottom Layer w10: v1@1368.84,-1568 1497,-1568 v2(1528,-1599) ; v1@1372.82,-1571.98 cw(c1382.43,-1581.59) 1382.43,-1568 ; v1@1372.82,-1562.35 ccw(c1386.46,-1548.71) 1386.46,-1568 ; v2@1513.31,-1599 ccw(c1477.86,-1599) 1502.93,-1573.93 ccw(c1528,-1548.86) v2@1528,-1584.31
  Bottom Layer w20: CN1.1@0,0 69,69 386,69 415.61,69 515,168.39 515,442 CN2.1@208,749 209,750 v2(1385,750) ; CN1.1@0,26.42 ccw(c0,90.19) 45.1,45.1 ccw(c90.19,0) CN1.1@26.42,0 ; CN2.1@208,729.47 cw(c208,682.33) 241.34,715.66 cw(c274.67,749) CN2.1@227.53,749 ; CN2.1@221.81,735.19 cw(c257.56,699.44) 257.56,750 ; CN2.1@221.81,762.81 ccw(c252.73,793.73) 252.73,750 ; v2@1378.15,743.15 ccw(c1361.62,726.62) 1361.62,750 ccw(c1361.62,773.38) v2@1378.15,756.85 ; v2(1442,656) 1535.61,656 C13.2@1537,657.39 C12.2@1537,575.06 1598,514.06 R8.1@1598,490 R9.1@1598,405 ; v2@1445.65,-751.35 cw(c1429.12,-767.88) 1452.5,-767.88 cw(c1475.88,-767.88) v2@1459.35,-751.35 ; v2@1448.85,649.15 cw(c1465.38,632.62) 1465.38,656 cw(c1465.38,679.38) v2@1448.85,662.85 ; v2(1452.5,-744.5) 1452.5,-1393.5 1528,-1469 v2(1528,-1599) ; 1515.53,656 ccw(c1515.53,678.86) C13.2@1531.7,662.7 ; v2@1521.15,-1592.15 ccw(c1504.62,-1575.62) 1528,-1575.62 ccw(c1551.38,-1575.62) v2@1534.85,-1592.15 ; C12.2@1531.7,580.36 ccw(c1518.89,593.16) 1537,593.16 ccw(c1555.11,593.16) C12.2@1542.3,580.36 ; C13.2@1531.7,652.09 cw(c1518.89,639.29) 1537,639.29 cw(c1555.11,639.29) C13.2@1542.3,652.09 ; C12.2@1537,567.56 cw(c1537,549.45) 1549.8,562.25 cw(c1562.61,575.06) C12.2@1544.5,575.06 ; 1568.19,543.87 cw(c1514.32,490) R8.1@1590.5,490 ; R9.1@1592.7,410.3 ccw(c1579.89,423.11) 1598,423.11 ccw(c1616.11,423.11) R9.1@1603.3,410.3 ; R8.1@1592.7,484.7 cw(c1579.89,471.89) 1598,471.89 cw(c1616.11,471.89) R8.1@1603.3,484.7 ; R8.1@1592.7,495.3 ccw(c1579.89,508.11) 1598,508.11 ccw(c1616.11,508.11) R8.1@1603.3,495.3 ; 1602.33,509.73 cw(c1582.6,490) R8.1@1610.5,490
pads on no net: P1. P1.A5 P1.A8 P1.B5 P1.B8 U1.4 U3.7 U3.8 U3.9 U3.10 U3.11 U3.12 U3.13 U3.14 U3.15

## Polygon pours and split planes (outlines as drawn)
GND on Top Layer "Top Layer-No Net" (solid, remove dead copper, pour order 1000): 165 vertices, not listed, extent -219,-2320 2688.96,1150.55
GND on Bottom Layer "Top Layer-No Net" (solid, remove dead copper, pour order 1001): 165 vertices, not listed, extent -219,-2321 2688.96,1149.55

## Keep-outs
Keep-Out Layer:
  lines w5: -218,-2242 -218,149.61 464.39,149.61 ; -218,1070.87 -218,189 468,189 cw(c461.39,169.85) 464.74,149.86 ; -217.95,-2241.01 ccw(c-139.21,-2241.01) -139.21,-2319.75 2610.22,-2319.75 ccw(c2610.22,-2241.01) 2688.96,-2241.01 2688.96,149.61 2607.39,149.61 1978.04,149.61 cw(c1978.04,169.29) 1978.04,188.98 2688.96,188.98 2688.96,989.72 2688.96,1070.81 ccw(c2610.22,1070.81) 2610.22,1149.55 2529.22,1149.55 ; -217.95,1070.81 cw(c-139.21,1070.81) -139.21,1149.55 2529.22,1149.61 ; 595,150 cw(c601.61,169.15) 598.26,189.14 ; 598.78,188.98 1350,188.98 ; 599,149.61 1347,149.61 ; 600,188.98 1348,188.98 ; 600.09,188.98 ccw(c600.09,169.29) 600.09,149.61 1348.12,149.61 ccw(c1348.12,169.29) 1348.12,188.98 ; 600.78,149.61 1352,149.61 ; 664,188.98 1277,188.98 ; 1350.74,149.86 ccw(c1347.39,169.85) 1354,189 ; 1525,150 cw(c1531.61,169.15) 1528.26,189.14 ; 1529,149.61 1816,149.61 ; 1531,188.98 1822,188.98 ; 1820.74,149.86 ccw(c1817.39,169.85) 1824,189 ; 1530.01,149.61 cw(c1530.01,169.29) 1530.01,188.98 1818.59,188.98 cw(c1818.59,169.29) 1818.59,149.61 1530.01,149.61
Mechanical 1:
  lines w5: 600.09,149.61 1348.12,149.61 ; 602,188.98 1351,188.98 ; 605,188.98 1348,188.98 ; 1346.88,149.61 600,149.61 1349.24,149.61 ; 1348.12,188.98 598.78,188.98 1350,188.98 ; 1528.01,149.61 1817.04,149.61 ; 1532.72,188.98 1818.59,188.98

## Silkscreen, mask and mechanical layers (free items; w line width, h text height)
Top Overlay:
  lines w5: 728.75,-199.67 1710,-199.67 1710,-520 729,-520 729,-199.67
  text "GND" at -3,862 h40
  text "GND" at 2347,848 h40
  text "VCC" at -49,737 h40
  text "GND" at -48,643 h40
  text "UART_TX" at 2049,563 h40
  text "SWDIO" at -48,537 h40
  text "UART_RX" at 2044,438 h40
  text "SWCLK" at -49,437 h40
  text "SWD" at 151,237 h40
  text "USER" at 1758,79 h40
  text "VMCU" at 2536,-23 h40
  text "5V" at 2255,-28 h40
  text "5V" at 155,-30 h40
  text "VMCU" at -204,-31 h40
  text "PB9" at 2539,-119 h40
  text "5V" at 2250,-121 h40
  text "PC11" at -174,-122 h40
  text "5V" at 164,-130 h40
  text "LITE-48" at 318,-157 h40
  text "PC0" at -160,-221 h40
  text "PB8" at 2539,-221 h40
  text "5V" at 2255,-226 h40
  text "5V" at 156,-228 h40
  text "HB1017A" at 318,-264 h40
  text "PC10" at 2539,-320 h40
  text "5V" at 158,-321 h40
  text "PC1" at -147,-324 h40
  text "5V" at 2259,-326 h40
  text "5V" at 2254,-419 h40
  text "PB7" at 2543,-419 h40
  text "PC2" at -160,-421 h40
  text "5V" at 156,-425 h40
  text "PC3" at -162,-513 h40
  text "5V" at 156,-518 h40
  text "PB6" at 2539,-522 h40
  text "5V" at 2255,-524 h40
  text "PC4" at -159,-614 h40
  text "5V" at 2255,-619 h40
  text "5V" at 155,-621 h40
  text "PB5" at 2539,-621 h40
  text "VCC_MCU" at 1190,-649 h40 r270
  text "3V3" at 1084,-650 h40 r270
  text "5V" at 1291,-651 h40 r270
  text "PC5" at -158,-713 h40
  text "5V" at 155,-716 h40
  text "5V" at 2254,-722 h40
  text "PB4" at 2539,-725 h40
  text "PA0" at -159,-816 h40
  text "PB3" at 2537,-817 h40
  text "3V3" at 154,-819 h40
  text "3V3" at 2225,-822 h40
  text "PA1" at -141,-916 h40
  text "3V3" at 2217,-916 h40
  text "PA15" at 2540,-920 h40
  text "3V3" at 155,-927 h40
  text "PA2" at -158,-1014 h40
  text "3V3" at 154,-1020 h40
  text "3V3" at 2226,-1020 h40
  text "PA14" at 2536,-1020 h40
  text "3V3" at 156,-1120 h40
  text "PC9" at 2538,-1121 h40
  text "PA3" at -158,-1122 h40
  text "3V3" at 2225,-1125 h40
  text "PA4" at -159,-1218 h40
  text "3V3" at 2222,-1222 h40
  text "3V3" at 160,-1225 h40
  text "PC8" at 2539,-1226 h40
  text "PA5" at -157,-1317 h40
  text "3V3" at 2226,-1317 h40
  text "PA13" at 2537,-1319 h40
  text "3V3" at 156,-1325 h40
  text "PA6" at -155,-1413 h40
  text "3V3" at 158,-1419 h40
  text "PA12" at 2537,-1420 h40
  text "3V3" at 2225,-1422 h40
  text "PA11" at 2537,-1516 h40
  text "3V3" at 156,-1518 h40
  text "PA7" at -159,-1519 h40
  text "3V3" at 2225,-1520 h40
  text "PB0" at -155,-1617 h40
  text "GND" at 2220,-1617 h40
  text "PA10" at 2538,-1620 h40
  text "GND" at 156,-1622 h40
  text "PB1" at -137,-1720 h40
  text "GND" at 158,-1720 h40
  text "PA9" at 2537,-1722 h40
  text "GND" at 2219,-1725 h40
  text "GND" at 156,-1819 h40
  text "GND" at 2220,-1819 h40
  text "PB2" at -155,-1820 h40
  text "PA8" at 2537,-1824 h40
  text "PB10" at -183,-1916 h40
  text "GND" at 2221,-1916 h40
  text "GND" at 156,-1917 h40
  text "PB15" at 2537,-1920 h40
  text "GND" at 156,-2017 h40
  text "PB11" at -166,-2019 h40
  text "PB14" at 2536,-2021 h40
  text "GND" at 2220,-2023 h40
  text "GND" at 157,-2116 h40
  text "GND" at 2220,-2120 h40
  text "PB12" at -182,-2122 h40
  text "PB13" at 2536,-2124 h40
  text "GND" at -159,-2215 h40
  text "GND" at 157,-2216 h40
  text "GND" at 2537,-2217 h40
  text "GND" at 2222,-2224 h40
Mechanical 1:
  lines w5: 1346.77,150.12 ccw(c1346.88,170.12) 1353.15,189.12 ; 1353.24,188.6 1353.32,188.58 ; 1816.93,149.59 ccw(c1817.04,170.09) 1823.46,189.56 ; 1823.52,189.55 1823.53,189.55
